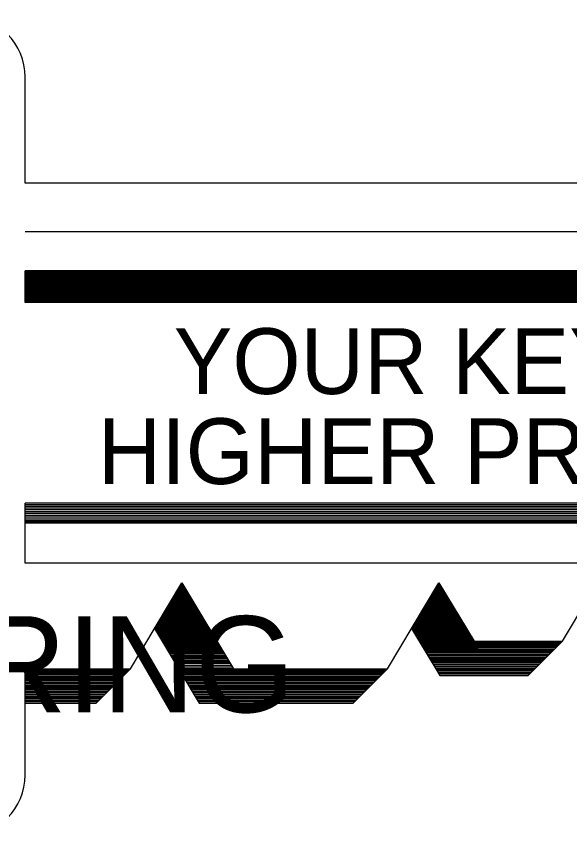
# Model space of a CAD drawing. Extents: x -11983 to -11903, y -13969.5 to -13913.5.
# Drawn here: x -11976.865 to -11975.725, y -13967.433 to -13965.746 of the extents above; entities that cross this region are included whole.
import ezdxf

# ---------------------------------------------------------------- set-up
doc = ezdxf.new("R2010")
doc.units = 0
doc.layers.add('Level 2', color=7, linetype='Continuous')

msp = doc.modelspace()

# ---------------------------------------------------------------- linework, layer by layer
at = {"layer": 'Level 2'}
for p, q in [((-11976.8471, -13966.0894), (-11976.8471, -13965.8706)), ((-11974.8051, -13966.0894), (-11976.8471, -13966.0894)), ((-11974.6841, -13966.1894), (-11976.8471, -13966.1894)), ((-11976.8471, -13966.3351), (-11976.8471, -13966.2699)), ((-11974.5868, -13966.2699), (-11976.8471, -13966.2699)), ((-11974.5848, -13966.2714), (-11976.8471, -13966.2714)), ((-11974.5831, -13966.2729), (-11976.8471, -13966.2729)), ((-11974.5811, -13966.2746), (-11976.8471, -13966.2746)), ((-11974.5788, -13966.2764), (-11976.8471, -13966.2764)), ((-11974.5768, -13966.2781), (-11976.8471, -13966.2781)), ((-11974.5743, -13966.2801), (-11976.8471, -13966.2801)), ((-11974.5723, -13966.2819), (-11976.8471, -13966.2819)), ((-11974.5698, -13966.2839), (-11976.8471, -13966.2839)), ((-11974.5673, -13966.2859), (-11976.8471, -13966.2859)), ((-11974.5653, -13966.2876), (-11976.8471, -13966.2876)), ((-11974.5631, -13966.2896), (-11976.8471, -13966.2896)), ((-11974.5603, -13966.2916), (-11976.8471, -13966.2916)), ((-11974.5583, -13966.2934), (-11976.8471, -13966.2934)), ((-11974.5563, -13966.2951), (-11976.8471, -13966.2951)), ((-11974.5538, -13966.2971), (-11976.8471, -13966.2971)), ((-11974.5513, -13966.2991), (-11976.8471, -13966.2991)), ((-11974.5491, -13966.3011), (-11976.8471, -13966.3011)), ((-11974.5463, -13966.3034), (-11976.8471, -13966.3034)), ((-11974.5441, -13966.3051), (-11976.8471, -13966.3051)), ((-11974.5418, -13966.3071), (-11976.8471, -13966.3071)), ((-11974.5391, -13966.3094), (-11976.8471, -13966.3094)), ((-11974.5366, -13966.3114), (-11976.8471, -13966.3114)), ((-11974.5348, -13966.3129), (-11976.8471, -13966.3129)), ((-11974.5323, -13966.3149), (-11976.8471, -13966.3149)), ((-11974.5301, -13966.3169), (-11976.8471, -13966.3169)), ((-11974.5278, -13966.3186), (-11976.8471, -13966.3186)), ((-11974.5258, -13966.3204), (-11976.8471, -13966.3204)), ((-11974.5238, -13966.3219), (-11976.8471, -13966.3219)), ((-11974.5211, -13966.3241), (-11976.8471, -13966.3241)), ((-11974.5193, -13966.3256), (-11976.8471, -13966.3256)), ((-11974.5173, -13966.3274), (-11976.8471, -13966.3274)), ((-11974.5156, -13966.3289), (-11976.8471, -13966.3289)), ((-11974.5136, -13966.3304), (-11976.8471, -13966.3304)), ((-11974.5121, -13966.3316), (-11976.8471, -13966.3316)), ((-11974.5103, -13966.3331), (-11976.8471, -13966.3331)), ((-11974.5091, -13966.3341), (-11976.8471, -13966.3341)), ((-11974.5078, -13966.3351), (-11976.8471, -13966.3351)), ((-11974.3921, -13966.7481), (-11976.8471, -13966.7481)), ((-11976.8471, -13966.8721), (-11976.8471, -13966.7481)), ((-11974.3961, -13966.7514), (-11976.8471, -13966.7514)), ((-11974.4003, -13966.7549), (-11976.8471, -13966.7549)), ((-11974.4051, -13966.7589), (-11976.8471, -13966.7589)), ((-11974.4091, -13966.7621), (-11976.8471, -13966.7621)), ((-11974.4138, -13966.7661), (-11976.8471, -13966.7661)), ((-11974.4181, -13966.7696), (-11976.8471, -13966.7696)), ((-11974.4226, -13966.7734), (-11976.8471, -13966.7734)), ((-11974.4276, -13966.7774), (-11976.8471, -13966.7774)), ((-11974.4321, -13966.7811), (-11976.8471, -13966.7811)), ((-11974.4363, -13966.7846), (-11976.8471, -13966.7846)), ((-11974.4393, -13966.7871), (-11976.8471, -13966.7871)), ((-11974.4421, -13966.7894), (-11976.8471, -13966.7894)), ((-11974.5421, -13966.8721), (-11976.8471, -13966.8721)), ((-11976.6303, -13967.0894), (-11976.5241, -13966.9121)), ((-11976.5241, -13966.9121), (-11976.4181, -13967.0894)), ((-11976.1006, -13967.0894), (-11975.9946, -13966.9121)), ((-11975.9958, -13966.9141), (-11975.9933, -13966.9141)), ((-11975.9946, -13966.9121), (-11975.9223, -13967.0324)), ((-11975.7403, -13967.0324), (-11975.6683, -13966.9121)), ((-11976.5351, -13966.9306), (-11976.5131, -13966.9306)), ((-11976.5341, -13966.9286), (-11976.5143, -13966.9286)), ((-11976.5328, -13966.9266), (-11976.5153, -13966.9266)), ((-11976.5316, -13966.9246), (-11976.5166, -13966.9246)), ((-11976.5303, -13966.9226), (-11976.5178, -13966.9226)), ((-11976.5291, -13966.9206), (-11976.5191, -13966.9206)), ((-11976.5281, -13966.9186), (-11976.5201, -13966.9186)), ((-11976.5268, -13966.9166), (-11976.5213, -13966.9166)), ((-11976.5256, -13966.9146), (-11976.5226, -13966.9146)), ((-11976.0056, -13966.9306), (-11975.9836, -13966.9306)), ((-11976.0046, -13966.9286), (-11975.9848, -13966.9286)), ((-11976.0033, -13966.9266), (-11975.9858, -13966.9266)), ((-11976.0021, -13966.9246), (-11975.9871, -13966.9246)), ((-11976.0008, -13966.9226), (-11975.9883, -13966.9226)), ((-11975.9996, -13966.9206), (-11975.9896, -13966.9206)), ((-11975.9986, -13966.9186), (-11975.9906, -13966.9186)), ((-11975.9976, -13966.9171), (-11975.9916, -13966.9171)), ((-11975.9966, -13966.9156), (-11975.9926, -13966.9156)), ((-11976.5446, -13966.9466), (-11976.5033, -13966.9466)), ((-11976.5433, -13966.9446), (-11976.5046, -13966.9446)), ((-11976.5421, -13966.9426), (-11976.5058, -13966.9426)), ((-11976.5408, -13966.9406), (-11976.5071, -13966.9406)), ((-11976.5401, -13966.9386), (-11976.5083, -13966.9386)), ((-11976.5388, -13966.9366), (-11976.5093, -13966.9366)), ((-11976.5376, -13966.9346), (-11976.5106, -13966.9346)), ((-11976.5363, -13966.9326), (-11976.5118, -13966.9326)), ((-11976.0151, -13966.9466), (-11975.9738, -13966.9466)), ((-11976.0138, -13966.9446), (-11975.9751, -13966.9446)), ((-11976.0126, -13966.9426), (-11975.9763, -13966.9426)), ((-11976.0113, -13966.9406), (-11975.9776, -13966.9406)), ((-11976.0106, -13966.9386), (-11975.9788, -13966.9386)), ((-11976.0093, -13966.9366), (-11975.9798, -13966.9366)), ((-11976.0081, -13966.9346), (-11975.9811, -13966.9346)), ((-11976.0068, -13966.9326), (-11975.9823, -13966.9326)), ((-11976.5556, -13966.9646), (-11976.4926, -13966.9646)), ((-11976.5543, -13966.9626), (-11976.4938, -13966.9626)), ((-11976.5531, -13966.9606), (-11976.4951, -13966.9606)), ((-11976.5518, -13966.9586), (-11976.4963, -13966.9586)), ((-11976.5508, -13966.9566), (-11976.4976, -13966.9566)), ((-11976.5496, -13966.9546), (-11976.4986, -13966.9546)), ((-11976.5483, -13966.9526), (-11976.4998, -13966.9526)), ((-11976.5471, -13966.9506), (-11976.5011, -13966.9506)), ((-11976.5458, -13966.9486), (-11976.5023, -13966.9486)), ((-11976.0261, -13966.9646), (-11975.9631, -13966.9646)), ((-11976.0248, -13966.9626), (-11975.9643, -13966.9626)), ((-11976.0236, -13966.9606), (-11975.9656, -13966.9606)), ((-11976.0223, -13966.9586), (-11975.9668, -13966.9586)), ((-11976.0213, -13966.9566), (-11975.9681, -13966.9566)), ((-11976.0201, -13966.9546), (-11975.9691, -13966.9546)), ((-11976.0188, -13966.9526), (-11975.9703, -13966.9526)), ((-11976.0176, -13966.9506), (-11975.9716, -13966.9506)), ((-11976.0163, -13966.9486), (-11975.9728, -13966.9486)), ((-11976.5648, -13966.9806), (-11976.4831, -13966.9806)), ((-11976.5636, -13966.9786), (-11976.4843, -13966.9786)), ((-11976.5623, -13966.9766), (-11976.4856, -13966.9766)), ((-11976.5611, -13966.9746), (-11976.4866, -13966.9746)), ((-11976.5603, -13966.9726), (-11976.4878, -13966.9726)), ((-11976.5591, -13966.9706), (-11976.4891, -13966.9706)), ((-11976.5578, -13966.9686), (-11976.4903, -13966.9686)), ((-11976.5568, -13966.9666), (-11976.4916, -13966.9666)), ((-11976.0353, -13966.9806), (-11975.9536, -13966.9806)), ((-11976.0341, -13966.9786), (-11975.9548, -13966.9786)), ((-11976.0328, -13966.9766), (-11975.9561, -13966.9766)), ((-11976.0316, -13966.9746), (-11975.9571, -13966.9746)), ((-11976.0308, -13966.9726), (-11975.9583, -13966.9726)), ((-11976.0296, -13966.9706), (-11975.9596, -13966.9706)), ((-11976.0283, -13966.9686), (-11975.9608, -13966.9686)), ((-11976.0273, -13966.9666), (-11975.9621, -13966.9666)), ((-11976.5758, -13966.9986), (-11976.4723, -13966.9986)), ((-11976.5748, -13966.9966), (-11976.4736, -13966.9966)), ((-11976.5736, -13966.9946), (-11976.4748, -13966.9946)), ((-11976.5723, -13966.9926), (-11976.4758, -13966.9926)), ((-11976.5711, -13966.9906), (-11976.4771, -13966.9906)), ((-11976.5698, -13966.9886), (-11976.4783, -13966.9886)), ((-11976.5686, -13966.9866), (-11976.4796, -13966.9866)), ((-11976.5673, -13966.9846), (-11976.4808, -13966.9846)), ((-11976.5661, -13966.9826), (-11976.4818, -13966.9826)), ((-11976.0463, -13966.9986), (-11975.9428, -13966.9986)), ((-11976.0453, -13966.9966), (-11975.9441, -13966.9966)), ((-11976.0441, -13966.9946), (-11975.9453, -13966.9946)), ((-11976.0428, -13966.9926), (-11975.9463, -13966.9926)), ((-11976.0416, -13966.9906), (-11975.9476, -13966.9906)), ((-11976.0403, -13966.9886), (-11975.9488, -13966.9886)), ((-11976.0391, -13966.9866), (-11975.9501, -13966.9866)), ((-11976.0378, -13966.9846), (-11975.9513, -13966.9846)), ((-11976.0366, -13966.9826), (-11975.9523, -13966.9826)), ((-11976.5806, -13967.0066), (-11976.4888, -13967.1601)), ((-11976.5806, -13967.0066), (-11976.4676, -13967.0066)), ((-11976.5796, -13967.0046), (-11976.4688, -13967.0046)), ((-11976.5793, -13967.0086), (-11976.4663, -13967.0086)), ((-11976.5783, -13967.0026), (-11976.4701, -13967.0026)), ((-11976.5781, -13967.0106), (-11976.4651, -13967.0106)), ((-11976.5771, -13967.0006), (-11976.4711, -13967.0006)), ((-11976.5771, -13967.0126), (-11976.4641, -13967.0126)), ((-11976.5758, -13967.0146), (-11976.4628, -13967.0146)), ((-11976.0511, -13967.0066), (-11975.9931, -13967.1031)), ((-11976.0511, -13967.0066), (-11975.9381, -13967.0066)), ((-11976.0501, -13967.0046), (-11975.9393, -13967.0046)), ((-11976.0498, -13967.0086), (-11975.9368, -13967.0086)), ((-11976.0488, -13967.0026), (-11975.9406, -13967.0026)), ((-11976.0486, -13967.0106), (-11975.9356, -13967.0106)), ((-11976.0476, -13967.0006), (-11975.9416, -13967.0006)), ((-11976.0476, -13967.0126), (-11975.9346, -13967.0126)), ((-11976.0463, -13967.0146), (-11975.9333, -13967.0146)), ((-11976.5746, -13967.0166), (-11976.4621, -13967.0166)), ((-11976.5733, -13967.0186), (-11976.4608, -13967.0186)), ((-11976.5723, -13967.0206), (-11976.4596, -13967.0206)), ((-11976.5711, -13967.0226), (-11976.4583, -13967.0226)), ((-11976.5698, -13967.0246), (-11976.4571, -13967.0246)), ((-11976.5686, -13967.0266), (-11976.4558, -13967.0266)), ((-11976.5673, -13967.0286), (-11976.4546, -13967.0286)), ((-11976.5663, -13967.0306), (-11976.4533, -13967.0306)), ((-11976.0451, -13967.0166), (-11975.9326, -13967.0166)), ((-11976.0438, -13967.0186), (-11975.9313, -13967.0186)), ((-11976.0428, -13967.0206), (-11975.9301, -13967.0206)), ((-11976.0416, -13967.0226), (-11975.9288, -13967.0226)), ((-11976.0403, -13967.0246), (-11975.9276, -13967.0246)), ((-11976.0391, -13967.0266), (-11975.9263, -13967.0266)), ((-11976.0378, -13967.0286), (-11975.9251, -13967.0286)), ((-11976.0368, -13967.0306), (-11975.9238, -13967.0306)), ((-11975.9223, -13967.0324), (-11975.7403, -13967.0324)), ((-11975.8111, -13967.1031), (-11975.7403, -13967.0324)), ((-11976.5651, -13967.0326), (-11976.4521, -13967.0326)), ((-11976.5638, -13967.0346), (-11976.4508, -13967.0346)), ((-11976.5628, -13967.0361), (-11976.4498, -13967.0361)), ((-11976.5618, -13967.0381), (-11976.4488, -13967.0381)), ((-11976.5606, -13967.0401), (-11976.4476, -13967.0401)), ((-11976.5593, -13967.0424), (-11976.4461, -13967.0424)), ((-11976.5578, -13967.0449), (-11976.4446, -13967.0449)), ((-11976.5563, -13967.0471), (-11976.4433, -13967.0471)), ((-11976.0356, -13967.0326), (-11975.9226, -13967.0326)), ((-11976.0343, -13967.0346), (-11975.9213, -13967.0346)), ((-11976.0333, -13967.0361), (-11975.9203, -13967.0361)), ((-11976.0323, -13967.0381), (-11975.9193, -13967.0381)), ((-11976.0311, -13967.0401), (-11975.9181, -13967.0401)), ((-11976.0298, -13967.0424), (-11975.9166, -13967.0424)), ((-11976.0283, -13967.0449), (-11975.9151, -13967.0449)), ((-11976.0268, -13967.0471), (-11975.9138, -13967.0471)), ((-11976.0261, -13967.0481), (-11975.7561, -13967.0481)), ((-11975.9571, -13967.0349), (-11975.7428, -13967.0349)), ((-11975.9571, -13967.0371), (-11975.7451, -13967.0371)), ((-11975.9571, -13967.0394), (-11975.7473, -13967.0394)), ((-11975.9571, -13967.0421), (-11975.7501, -13967.0421)), ((-11975.9571, -13967.0449), (-11975.7528, -13967.0449)), ((-11976.5548, -13967.0499), (-11976.4416, -13967.0499)), ((-11976.5533, -13967.0524), (-11976.4403, -13967.0524)), ((-11976.5513, -13967.0554), (-11976.4383, -13967.0554)), ((-11976.5498, -13967.0581), (-11976.4368, -13967.0581)), ((-11976.5481, -13967.0611), (-11976.4351, -13967.0611)), ((-11976.5463, -13967.0641), (-11976.4331, -13967.0641)), ((-11976.0243, -13967.0511), (-11975.7591, -13967.0511)), ((-11976.0226, -13967.0541), (-11975.7621, -13967.0541)), ((-11976.0208, -13967.0569), (-11975.7648, -13967.0569)), ((-11976.0191, -13967.0599), (-11975.7678, -13967.0599)), ((-11976.0173, -13967.0629), (-11975.7708, -13967.0629)), ((-11976.0156, -13967.0659), (-11975.7738, -13967.0659)), ((-11976.5448, -13967.0666), (-11976.4316, -13967.0666)), ((-11976.5433, -13967.0691), (-11976.4301, -13967.0691)), ((-11976.5413, -13967.0721), (-11976.4283, -13967.0721)), ((-11976.5398, -13967.0749), (-11976.4268, -13967.0749)), ((-11976.5381, -13967.0779), (-11976.4251, -13967.0779)), ((-11976.5356, -13967.0819), (-11976.4226, -13967.0819)), ((-11976.0136, -13967.0689), (-11975.7768, -13967.0689)), ((-11976.0126, -13967.0709), (-11975.7788, -13967.0709)), ((-11976.0111, -13967.0731), (-11975.7811, -13967.0731)), ((-11976.0093, -13967.0761), (-11975.7841, -13967.0761)), ((-11976.0076, -13967.0791), (-11975.7871, -13967.0791)), ((-11976.0061, -13967.0816), (-11975.7896, -13967.0816)), ((-11976.8471, -13967.3081), (-11976.8471, -13967.0894)), ((-11976.8471, -13967.0894), (-11976.6303, -13967.0894)), ((-11976.8471, -13967.0919), (-11976.6328, -13967.0919)), ((-11976.8471, -13967.0941), (-11976.6351, -13967.0941)), ((-11976.8471, -13967.0964), (-11976.6373, -13967.0964)), ((-11976.8471, -13967.0991), (-11976.6401, -13967.0991)), ((-11976.7011, -13967.1601), (-11976.6303, -13967.0894)), ((-11976.5336, -13967.0851), (-11976.4206, -13967.0851)), ((-11976.5316, -13967.0886), (-11976.4186, -13967.0886)), ((-11976.5296, -13967.0919), (-11976.1031, -13967.0919)), ((-11976.5283, -13967.0941), (-11976.1053, -13967.0941)), ((-11976.5268, -13967.0964), (-11976.1076, -13967.0964)), ((-11976.5253, -13967.0991), (-11976.1103, -13967.0991)), ((-11976.4181, -13967.0894), (-11976.1006, -13967.0894)), ((-11976.1713, -13967.1601), (-11976.1006, -13967.0894)), ((-11976.0041, -13967.0849), (-11975.7928, -13967.0849)), ((-11976.0023, -13967.0879), (-11975.7958, -13967.0879)), ((-11976.0003, -13967.0909), (-11975.7988, -13967.0909)), ((-11975.9988, -13967.0936), (-11975.8016, -13967.0936)), ((-11975.9966, -13967.0971), (-11975.8051, -13967.0971)), ((-11976.8471, -13967.1019), (-11976.6428, -13967.1019)), ((-11976.8471, -13967.1051), (-11976.6461, -13967.1051)), ((-11976.8471, -13967.1081), (-11976.6491, -13967.1081)), ((-11976.8471, -13967.1111), (-11976.6521, -13967.1111)), ((-11976.8471, -13967.1139), (-11976.6548, -13967.1139)), ((-11976.8471, -13967.1169), (-11976.6578, -13967.1169)), ((-11976.5236, -13967.1019), (-11976.1131, -13967.1019)), ((-11976.5216, -13967.1051), (-11976.1163, -13967.1051)), ((-11976.5198, -13967.1081), (-11976.1193, -13967.1081)), ((-11976.5181, -13967.1111), (-11976.1223, -13967.1111)), ((-11976.5166, -13967.1139), (-11976.1251, -13967.1139)), ((-11976.5146, -13967.1169), (-11976.1281, -13967.1169)), ((-11975.9948, -13967.1001), (-11975.8081, -13967.1001)), ((-11975.9931, -13967.1031), (-11975.8111, -13967.1031)), ((-11976.8471, -13967.1199), (-11976.6608, -13967.1199)), ((-11976.8471, -13967.1229), (-11976.6638, -13967.1229)), ((-11976.8471, -13967.1259), (-11976.6668, -13967.1259)), ((-11976.8471, -13967.1279), (-11976.6688, -13967.1279)), ((-11976.8471, -13967.1301), (-11976.6711, -13967.1301)), ((-11976.8471, -13967.1331), (-11976.6741, -13967.1331)), ((-11976.5128, -13967.1199), (-11976.1311, -13967.1199)), ((-11976.5111, -13967.1229), (-11976.1341, -13967.1229)), ((-11976.5093, -13967.1259), (-11976.1371, -13967.1259)), ((-11976.5081, -13967.1279), (-11976.1391, -13967.1279)), ((-11976.5068, -13967.1301), (-11976.1413, -13967.1301)), ((-11976.5051, -13967.1331), (-11976.1443, -13967.1331)), ((-11976.8471, -13967.1361), (-11976.6771, -13967.1361)), ((-11976.8471, -13967.1386), (-11976.6796, -13967.1386)), ((-11976.8471, -13967.1419), (-11976.6828, -13967.1419)), ((-11976.8471, -13967.1449), (-11976.6858, -13967.1449)), ((-11976.8471, -13967.1479), (-11976.6888, -13967.1479)), ((-11976.8471, -13967.1506), (-11976.6916, -13967.1506)), ((-11976.5031, -13967.1361), (-11976.1473, -13967.1361)), ((-11976.5016, -13967.1386), (-11976.1498, -13967.1386)), ((-11976.4998, -13967.1419), (-11976.1531, -13967.1419)), ((-11976.4978, -13967.1449), (-11976.1561, -13967.1449)), ((-11976.4961, -13967.1479), (-11976.1591, -13967.1479)), ((-11976.4946, -13967.1506), (-11976.1618, -13967.1506)), ((-11976.8471, -13967.1541), (-11976.6951, -13967.1541)), ((-11976.8471, -13967.1571), (-11976.6981, -13967.1571)), ((-11976.8471, -13967.1601), (-11976.7011, -13967.1601)), ((-11976.4923, -13967.1541), (-11976.1653, -13967.1541)), ((-11976.4906, -13967.1571), (-11976.1683, -13967.1571)), ((-11976.4888, -13967.1601), (-11976.1713, -13967.1601))]:
    msp.add_line(p, q, dxfattribs=at)
for centre, start, end in [((-11976.9721, -13965.8706), 0, 90), ((-11976.9721, -13967.3081), 270, 0)]:
    msp.add_arc(centre, 0.125, start, end, dxfattribs=at)

# ---------------------------------------------------------------- texts
for s, height, p in [('YOUR KEY TO', 0.135374, (-11976.5411, -13966.5234)), ('HIGHER PROFITS', 0.135374, (-11976.6976, -13966.7089)), ('ENGINEERING', 0.197985, (-11978.1448, -13967.1791))]:
    msp.add_text(s, height=height, dxfattribs=at).set_placement(p)

doc.saveas('drawing.dxf')
